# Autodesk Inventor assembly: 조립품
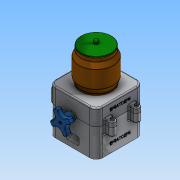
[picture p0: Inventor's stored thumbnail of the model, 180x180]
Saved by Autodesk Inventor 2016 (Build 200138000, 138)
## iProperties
Created: 2018-01
Part Number: 조립품
Material: 일반
Document SubType Name: Assembly
Designer: Administrator
Author: Administrator
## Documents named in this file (9)
- C:\Users\Administrator\Desktop\480107V1019\조립품.iam
- C:\Users\Administrator\Desktop\480107V1019\본체.ipt
- C:\Users\Administrator\Desktop\480107V1019\본체커버.ipt
- C:\Users\Administrator\Desktop\480107V1019\용기.ipt
- C:\Users\Administrator\Desktop\480107V1019\용기캡.ipt
- C:\Users\Administrator\Desktop\480107V1019\볼트 M4x12.ipt
- C:\Users\Administrator\Desktop\480107V1019\핸들축.ipt
- C:\Users\Administrator\Desktop\480107V1019\핸들.ipt
- C:\Users\Administrator\Desktop\480107V1019\볼트 M3x12.ipt
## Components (2 placed, 2 different names)
1. 핸들축:1
2. 핸들:1
